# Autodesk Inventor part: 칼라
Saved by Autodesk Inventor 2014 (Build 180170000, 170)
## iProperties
Created: 2026-07
Part Number: 칼라
Material: 일반
Document SubType Name: Modeling
Designer: dg
Density: 1 g/cm^3
Appearance: 기본값
Author: dg
Author: jhkim
Creation Date: 2026-07-02
Sending System: Autodesk Inventor 2027
Preprocessor: ST-DEVELOPER v20.1
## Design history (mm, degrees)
node "칼라1"
node "솔리드1"
node "기준1"
